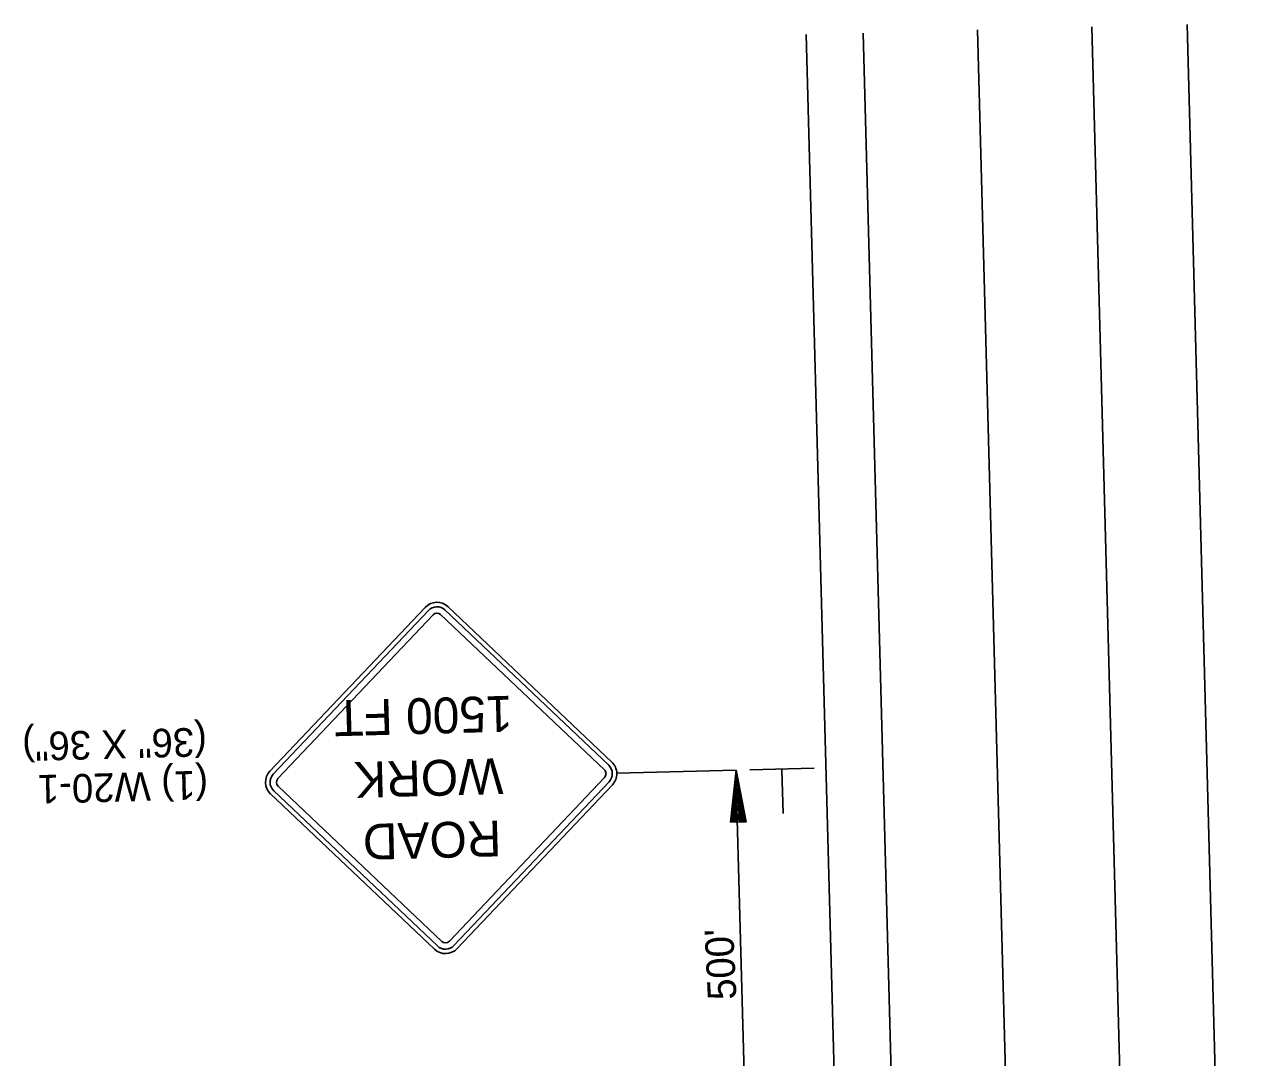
# Model space of a CAD drawing. Extents: x 1929653 to 1931621, y 596452 to 600944.
# Drawn here: x 1930632.3 to 1930887.4, y 600727.6 to 600943.9 of the extents above; entities that cross this region are included whole.
import ezdxf

# ---------------------------------------------------------------- set-up
doc = ezdxf.new("R2010")
doc.units = 0
for name, color, linetype in [('P_TC_Signs_Temporary', 7, 'Continuous'), ('R_Border', 7, 'Continuous'), ('R_Draft', 7, 'Continuous')]:
    doc.layers.add(name, color=color, linetype=linetype)

msp = doc.modelspace()

# ---------------------------------------------------------------- linework, layer by layer
at = {"layer": 'P_TC_Signs_Temporary'}
for p, q in [((1930683.7, 600787.56), (1930716.21, 600821.86)), ((1930684.38, 600786.92), (1930716.89, 600821.21)), ((1930720.33, 600821.31), (1930754.63, 600788.8)), ((1930720.98, 600821.99), (1930755.27, 600789.48)), ((1930685.34, 600786.01), (1930717.84, 600820.31)), ((1930719.43, 600820.35), (1930753.73, 600787.85)), ((1930753.77, 600786.26), (1930721.27, 600751.96)), ((1930754.72, 600785.36), (1930722.22, 600751.06)), ((1930718.13, 600750.29), (1930683.83, 600782.79)), ((1930718.77, 600750.97), (1930684.48, 600783.47)), ((1930719.68, 600751.92), (1930685.38, 600784.42)), ((1930755.4, 600784.71), (1930722.9, 600750.42))]:
    msp.add_line(p, q, dxfattribs=at)
for centre, radius, start, end in [((1930718.66, 600819.54), 3.38, 46.5377, 136.5377), ((1930718.66, 600819.54), 2.44, 46.5377, 136.5377), ((1930718.66, 600819.54), 1.13, 46.5377, 136.5377), ((1930752.95, 600787.03), 1.12, 316.5377, 46.5377), ((1930752.95, 600787.03), 2.44, 316.5377, 46.5377), ((1930752.95, 600787.03), 3.38, 316.5377, 46.5377), ((1930686.15, 600785.24), 3.38, 136.5377, 226.5377), ((1930686.15, 600785.24), 2.44, 136.5377, 226.5377), ((1930686.15, 600785.24), 1.12, 136.5377, 226.5377), ((1930720.45, 600752.74), 1.13, 226.5377, 316.5377), ((1930720.45, 600752.74), 3.37, 226.5377, 316.5377), ((1930720.45, 600752.74), 2.44, 226.5377, 316.5377)]:
    msp.add_arc(centre, radius, start, end, dxfattribs=at)
at = {"layer": 'R_Draft'}
for p, q in [((1930855.8, 600943.38), (1930867.45, 600509.53)), ((1930875.75, 600943.92), (1930887.39, 600510.06)), ((1930795.98, 600941.77), (1930807.63, 600507.92)), ((1930807.95, 600942.1), (1930819.59, 600508.24)), ((1930831.88, 600942.74), (1930843.52, 600508.89)), ((1930756.33, 600787.12), (1930781.32, 600787.8)), ((1930780.16, 600776.86), (1930781.32, 600787.8)), ((1930784.01, 600687.71), (1930781.29, 600787.67)), ((1930783.42, 600776.99), (1930781.32, 600787.8)), ((1930784.19, 600787.87), (1930797.65, 600788.23)), ((1930790.89, 600787.86), (1930791.14, 600778.67)), ((1930780.42, 600776.87), (1930781.4, 600785.98)), ((1930783.14, 600776.98), (1930781.4, 600785.98)), ((1930780.7, 600776.88), (1930781.48, 600784.11)), ((1930782.87, 600776.97), (1930781.48, 600784.11)), ((1930780.98, 600776.89), (1930781.56, 600782.3)), ((1930781.26, 600776.9), (1930781.63, 600780.46)), ((1930782.59, 600776.96), (1930781.56, 600782.3)), ((1930782.32, 600776.95), (1930781.63, 600780.46)), ((1930781.53, 600776.91), (1930781.71, 600778.64)), ((1930782.04, 600776.93), (1930781.71, 600778.64)), ((1930780.16, 600776.86), (1930783.42, 600776.99))]:
    msp.add_line(p, q, dxfattribs=at)

# ---------------------------------------------------------------- texts
at = {"layer": 'P_TC_Signs_Temporary'}
for s, p in [('1500 FT', (1930734.39, 600803.37)), ('WORK', (1930732.44, 600790.29)), (' ROAD ', (1930734.82, 600777.33))]:
    msp.add_text(s, height=7.5, rotation=181.5377, dxfattribs=at).set_placement(p)
at = {"layer": 'R_Border'}
for s, p in [('(36" X 36")', (1930670.42, 600796.7)), ('(1) W20-1', (1930670.66, 600787.7))]:
    msp.add_text(s, height=6, rotation=181.5377, dxfattribs=at).set_placement(p)
at = {"layer": 'R_Draft'}
msp.add_text("500'", height=6, rotation=92.7681, dxfattribs=at).set_placement((1930781.41, 600739.82))

doc.saveas('drawing.dxf')
